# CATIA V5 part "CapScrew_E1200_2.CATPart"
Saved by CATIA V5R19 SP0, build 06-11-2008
Part number: CapScrew_E1200_2
Nomenclature: E 1200/4x25
Source: Unknown
Description: MEUSBURGER
Bounding box of the stored display mesh (mm): x -3.499 to 3.499, y -3.499 to 3.495, z 0 to 29
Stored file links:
  C:\Users\jsmid\Desktop\DP_Smidak_Forma LEGO\CapScrew_E1200_2.CATPart
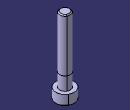
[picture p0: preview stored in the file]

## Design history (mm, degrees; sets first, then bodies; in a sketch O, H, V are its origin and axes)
Body1 (main body)
  Solid1 "PartBody": solid without history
